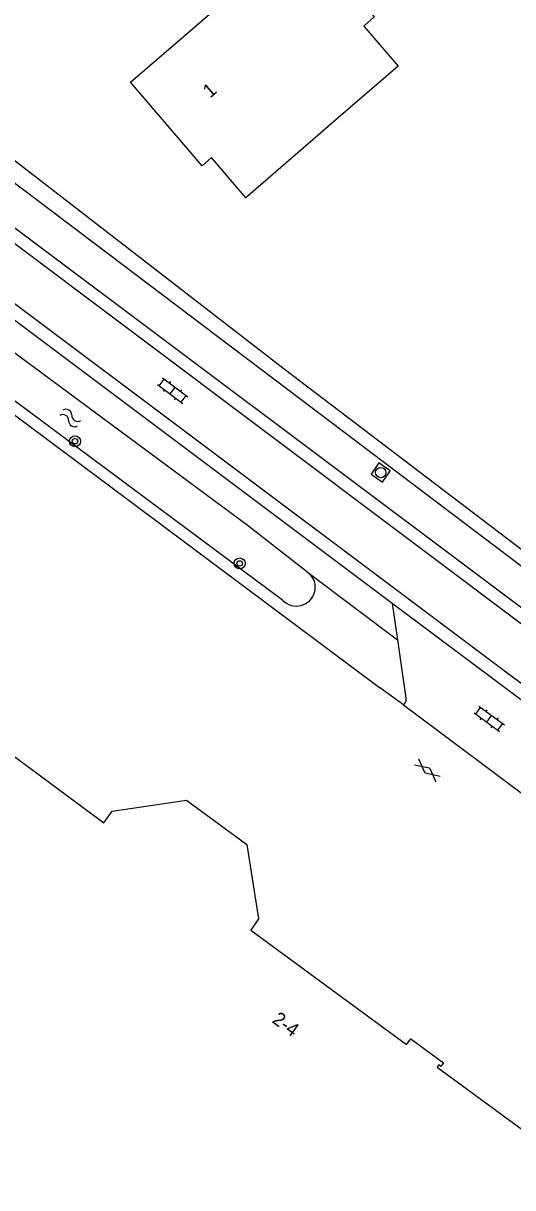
# Model space of a CAD drawing. Extents: x 126000 to 131009, y 393000 to 395500.
# Drawn here: x 130673.4 to 130709, y 393729.8 to 393814.5 of the extents above; entities that cross this region are included whole.
import ezdxf

# ---------------------------------------------------------------- set-up
doc = ezdxf.new("R2010")
doc.units = 0
for name, color, linetype in [('gg-anno-huisnummerreeks BGT', 7, 'Continuous'), ('gg-bbg-hoofdgebouw', 7, 'Continuous'), ('gg-knt-verharding', 7, 'Continuous'), ('gg-knt-verharding nz', 7, 'Continuous'), ('gg-kntw-bovenkant insteek waterloop', 7, 'Continuous'), ('gt-grn-groengrens', 7, 'Continuous'), ('gt-symb-boom', 7, 'Continuous'), ('gt-symb-gesloten verharding', 7, 'Continuous'), ('gt-symb-klinker verharding', 7, 'Continuous'), ('gt-symb-rioolschacht', 7, 'Continuous'), ('gt-symb-watersymbool', 7, 'Continuous')]:
    doc.layers.add(name, color=color, linetype=linetype)

# ---------------------------------------------------------------- blocks, each defined once
blk = doc.blocks.new('gt0-KL1')
at = {"layer": 'gt-symb-klinker verharding'}
for p, q in [((-1.15, 0.3), (1.15, 0.3)), ((-1, -0.3), (-1, 0.3)), ((-0.5, 0.3), (-0.5, 0.45)), ((0, -0.3), (0, 0.3)), ((0.5, 0.3), (0.5, 0.45)), ((1, -0.3), (1, 0.3)), ((-1.15, -0.3), (1.15, -0.3)), ((-0.5, -0.45), (-0.5, -0.3)), ((0.5, -0.45), (0.5, -0.3))]:
    blk.add_line(p, q, dxfattribs=at)
blk = doc.blocks.new('gt0-WA')
at = {"layer": 'gt-symb-watersymbool'}
for centre, start, end in [((-0.323, 0.022), 28.07249, 151.92751), ((0.427, 0.422), 208.07248, 331.92751), ((-0.323, -0.428), 28.07249, 151.92751), ((0.427, -0.028), 208.07248, 331.92751)]:
    blk.add_arc(centre, 0.425, start, end, dxfattribs=at)
blk = doc.blocks.new('gt0-GESVH1')
at = {"layer": 'gt-symb-gesloten verharding'}
for p, q in [((-0.992, -0.261), (0.008, 0.239)), ((0.008, -0.261), (-0.992, 0.239)), ((0.008, 0.239), (1.008, -0.261)), ((1.008, 0.239), (0.008, -0.261))]:
    blk.add_line(p, q, dxfattribs=at)
blk = doc.blocks.new('gt0-BOOM')
at = {"layer": 'gt-symb-boom'}
for radius in [0.4, 0.2]:
    blk.add_circle((0, 0), radius, dxfattribs=at)
blk = doc.blocks.new('gt0-RS')
at = {"layer": 'gt-symb-rioolschacht'}
blk.add_lwpolyline([(-0.5, -0.5), (0.5, -0.5), (0.5, 0.5), (-0.5, 0.5)], close=True, dxfattribs=at)
blk.add_circle((0, 0), 0.375, dxfattribs=at)

msp = doc.modelspace()

# ---------------------------------------------------------------- linework, layer by layer
at = {"layer": 'gg-bbg-hoofdgebouw'}
for points in [[(130687.1, 393804.728), (130686.42, 393804.14), (130681.21, 393810.22), (130693.72, 393821.02)], [(130693.72, 393821.02), (130698.94, 393814.97), (130698.17, 393814.3), (130700.69, 393811.39), (130696.32, 393807.62)], [(130696.32, 393807.62), (130689.591, 393801.815), (130687.1, 393804.728)], [(130667.951, 393764.693), (130679.262, 393756.321), (130679.864, 393757.151), (130685.265, 393757.956), (130689.66, 393754.727), (130690.525, 393749.314), (130689.95, 393748.505), (130701.288, 393740.18), (130701.596, 393740.599), (130703.983, 393738.845), (130703.786, 393738.577), (130703.63, 393738.691), (130703.512, 393738.53), (130710.442, 393733.468), (130710.561, 393733.629), (130710.392, 393733.754), (130710.583, 393734.011), (130712.949, 393732.256), (130712.654, 393731.825), (130718.463, 393727.547)]]:
    msp.add_lwpolyline(points, dxfattribs=at)
at = {"layer": 'gg-knt-verharding'}
for p, q in [((130700.244, 393772.285), (130658.096, 393803.88)), ((130652.794, 393800.917), (130699.318, 393766.165)), ((130718.198, 393758.816), (130700.244, 393772.285)), ((130700.244, 393772.285), (130700.63, 393769.62)), ((130701.062, 393764.89), (130699.318, 393766.165)), ((130701.062, 393764.89), (130710.791, 393757.61))]:
    msp.add_line(p, q, dxfattribs=at)
for points in [[(130718.012, 393765.701), (130673.26, 393799.24), (130662.88, 393807.073)], [(130700.63, 393769.62), (130701.241, 393765.396), (130701.231, 393765.183), (130701.152, 393764.984), (130701.062, 393764.89)]]:
    msp.add_lwpolyline(points, dxfattribs=at)
at = {"layer": 'gg-knt-verharding nz'}
msp.add_line((130633.603, 393827.887), (130898.384, 393629.136), dxfattribs=at)
msp.add_lwpolyline([(130628.561, 393821.673), (130636.106, 393820.631), (130641.9, 393817.25), (130896.345, 393626.519)], dxfattribs=at)
at = {"layer": 'gg-kntw-bovenkant insteek waterloop'}
msp.add_line((130692.265, 393772.526), (130667.313, 393791.068), dxfattribs=at)
msp.add_lwpolyline([(130668.661, 393793.556), (130689.779, 393777.939), (130694.002, 393774.627), (130694.19, 393774.485)], dxfattribs=at)
msp.add_arc((130693.271, 393773.463), 1.375, 222.96419, 48.0389, dxfattribs=at)
at = {"layer": 'gt-grn-groengrens'}
for p, q in [((130665.911, 393809.825), (130692.374, 393789.359)), ((130692.374, 393789.359), (130719.899, 393768.426)), ((130694.19, 393774.485), (130700.63, 393769.62))]:
    msp.add_line(p, q, dxfattribs=at)
msp.add_lwpolyline([(130665.911, 393809.825), (130665.251, 393808.544), (130718.978, 393767.946), (130719.899, 393768.426)], dxfattribs=at)

# ---------------------------------------------------------------- block references
at = {"layer": 'gt-symb-boom'}
for p in [(130677.158, 393784.088), (130689.145, 393775.193)]:
    msp.add_blockref('gt0-BOOM', p, dxfattribs=at)
at = {"layer": 'gt-symb-gesloten verharding', "rotation": -38.704570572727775}
msp.add_blockref('gt0-GESVH1', (130702.81, 393760.127), dxfattribs=at)
at = {"layer": 'gt-symb-klinker verharding'}
for p, rotation in [((130684.268, 393787.769), -36.78969964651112), ((130707.307, 393763.884), -36.17064413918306)]:
    msp.add_blockref('gt0-KL1', p, dxfattribs=dict(at, rotation=rotation))
at = {"layer": 'gt-symb-rioolschacht', "rotation": -124.69152882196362}
msp.add_blockref('gt0-RS', (130699.411, 393781.809), dxfattribs=at)
at = {"layer": 'gt-symb-watersymbool', "rotation": -30.384237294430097}
msp.add_blockref('gt0-WA', (130676.767, 393785.811), dxfattribs=at)

# ---------------------------------------------------------------- texts
at = {"layer": 'gg-anno-huisnummerreeks BGT'}
for s, rotation, p in [('1', 40.6, (130686.991, 393809.024)), ('2-4', 323.7, (130691.435, 393741.832))]:
    msp.add_text(s, height=1, rotation=rotation, dxfattribs=at).set_placement(p)

doc.saveas('drawing.dxf')
